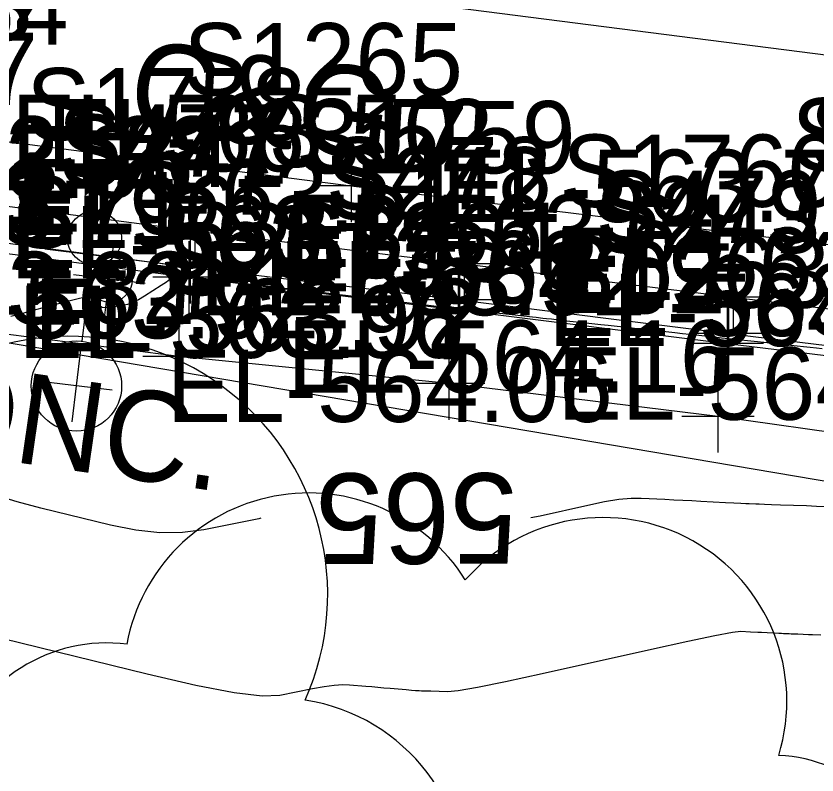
# Model space of a CAD drawing. Extents: x 1724534 to 1727318, y 657156 to 660047.
# Drawn here: x 1725337.13 to 1725381.44, y 658574.44 to 658616.4 of the extents above; entities that cross this region are included whole.
import ezdxf

# ---------------------------------------------------------------- set-up
doc = ezdxf.new("R2010")
doc.units = 0
for name, color, linetype in [('SURVEY - CONTOURS - Index with Text', 7, 'Continuous'), ('SURVEY - CONTOURS - Intermediate with optional Text', 7, 'Continuous'), ('SURVEY - DTM - Breaklines', 7, 'Continuous'), ('SURVEY - DTM - Breaklines - Points - Elevations', 7, 'Continuous'), ('SURVEY - DTM - Breaklines - Points - Locators', 7, 'Continuous'), ('SURVEY - DTM - Breaklines - Points - Numbers', 7, 'Continuous'), ('SURVEY - PROPERTY - Property Markers with Text', 7, 'Continuous'), ('SURVEY - TRAFFIC CONTROL - Pavement Marking - Points - Numbers', 7, 'Continuous'), ('SURVEY - TRAFFIC CONTROL - Pavement Marking with Text', 7, 'Continuous'), ('SURVEY - TRAFFIC CONTROL - Signs - Points - Elevations', 7, 'Continuous'), ('SURVEY - TRAFFIC CONTROL - Signs - Points - Locators', 7, 'Continuous'), ('SURVEY - TRAFFIC CONTROL - Signs - Points - Numbers', 7, 'Continuous'), ('SURVEY - TRAFFIC CONTROL - Signs and Devices with Text', 7, 'Continuous'), ('SURVEY - TRANSPORTATION - Features', 7, 'Continuous'), ('SURVEY - TRANSPORTATION - Features - Points - Elevations', 7, 'Continuous'), ('SURVEY - TRANSPORTATION - Features - Points - Locators', 7, 'Continuous'), ('SURVEY - TRANSPORTATION - Features - Points - Numbers', 7, 'Continuous'), ('SURVEY - TRANSPORTATION - Features Text', 7, 'Continuous'), ('SURVEY - TRANSPORTATION - Roads', 7, 'Continuous'), ('SURVEY - TRANSPORTATION - Roads - Points - Elevations', 7, 'Continuous'), ('SURVEY - TRANSPORTATION - Roads - Points - Locators', 7, 'Continuous'), ('SURVEY - TRANSPORTATION - Roads - Points - Numbers', 7, 'Continuous'), ('SURVEY - UTILITIES - Electric (Lighting) - Points - Elevations', 7, 'Continuous'), ('SURVEY - UTILITIES - Electric (Lighting) - Points - Locators', 7, 'Continuous'), ('SURVEY - UTILITIES - Electric (Lighting) - Points - Numbers', 7, 'Continuous'), ('SURVEY - UTILITIES - Electric (Lighting) with Text', 7, 'Continuous'), ('SURVEY - UTILITIES - Fiber Optic Cable (Underground) with Text', 7, 'Continuous'), ('SURVEY - UTILITIES - Gas - Points - Elevations', 7, 'Continuous'), ('SURVEY - UTILITIES - Gas - Points - Numbers', 7, 'Continuous'), ('SURVEY - VEGETATION - Features with Text', 7, 'Continuous')]:
    doc.layers.add(name, color=color, linetype=linetype)

msp = doc.modelspace()

# ---------------------------------------------------------------- linework, layer by layer
at = {"layer": 'SURVEY - CONTOURS - Index with Text'}
for points in [[(1725350.676, 658588.635), (1725350.563, 658588.614), (1725347.522, 658588.005), (1725346.343, 658587.849), (1725345.09, 658587.839), (1725343.76, 658587.974), (1725342.356, 658588.256), (1725338.508, 658589.2), (1725337.195, 658589.54), (1725336.141, 658589.853)], [(1725381.955, 658589.274), (1725381.401, 658589.295), (1725380.857, 658589.315), (1725379.417, 658589.37), (1725378.926, 658589.388), (1725378.536, 658589.403), (1725378.246, 658589.414), (1725378.056, 658589.421), (1725377.683, 658589.435), (1725377.496, 658589.443), (1725377.217, 658589.456), (1725376.846, 658589.474), (1725376.381, 658589.498), (1725375.019, 658589.568), (1725374.511, 658589.594), (1725374.008, 658589.62), (1725373.51, 658589.646), (1725373.017, 658589.671), (1725371.709, 658589.738), (1725371.157, 658589.733), (1725370.48, 658589.666), (1725369.679, 658589.538), (1725368.754, 658589.349), (1725366.12, 658588.762), (1725365.603, 658588.657)]]:
    msp.add_lwpolyline(points, dxfattribs=at)
at = {"layer": 'SURVEY - CONTOURS - Intermediate with optional Text'}
for points in [[(1725381.732, 658597.999), (1725381.415, 658598.033), (1725381.067, 658598.071), (1725380.687, 658598.112), (1725379.634, 658598.226), (1725379.244, 658598.268), (1725378.866, 658598.309), (1725378.498, 658598.349), (1725378.142, 658598.387), (1725376.681, 658598.543), (1725376.549, 658598.557), (1725376.505, 658598.562), (1725376.467, 658598.566), (1725376.351, 658598.579), (1725376.158, 658598.6), (1725375.888, 658598.629), (1725375.066, 658598.72), (1725374.741, 658598.755), (1725374.385, 658598.795), (1725373.996, 658598.838), (1725373.575, 658598.884), (1725372.409, 658599.013), (1725371.336, 658599.131), (1725371.084, 658599.159), (1725370.219, 658599.254), (1725369.883, 658599.291), (1725369.474, 658599.336), (1725368.991, 658599.389), (1725367.605, 658599.543), (1725367.132, 658599.595), (1725366.753, 658599.637), (1725366.468, 658599.668), (1725366.278, 658599.689), (1725365.895, 658599.731), (1725365.694, 658599.753), (1725364.404, 658599.896), (1725362.799, 658600.073), (1725361.896, 658600.173), (1725361.67, 658600.198), (1725361.595, 658600.206), (1725361.595, 658600.206), (1725361.586, 658600.207), (1725361.561, 658600.21), (1725361.52, 658600.215), (1725361.461, 658600.222), (1725361.284, 658600.242), (1725361.141, 658600.259), (1725360.845, 658600.294), (1725357.986, 658600.635), (1725357.386, 658600.706), (1725356.656, 658600.793), (1725356.525, 658600.809), (1725356.386, 658600.825), (1725356.254, 658600.84), (1725355.961, 658600.875), (1725355.509, 658600.929), (1725354.897, 658601.002), (1725353.05, 658601.222), (1725352.439, 658601.295), (1725351.992, 658601.348), (1725351.708, 658601.382), (1725351.363, 658601.423), (1725351.074, 658601.457), (1725349.995, 658601.586), (1725348.112, 658601.81), (1725347.494, 658601.884), (1725347.053, 658601.937), (1725346.788, 658601.968), (1725346.699, 658601.979), (1725346.698, 658601.979), (1725346.698, 658601.979), (1725346.698, 658601.979), (1725346.698, 658601.979), (1725346.698, 658601.979), (1725346.602, 658601.99), (1725346.483, 658602.004), (1725345.428, 658602.125), (1725345.725, 658601.996), (1725345.738, 658601.944), (1725345.648, 658601.844), (1725345.455, 658601.695), (1725345.159, 658601.499), (1725344.235, 658600.91), (1725343.898, 658600.712), (1725343.583, 658600.56), (1725343.289, 658600.454), (1725343.016, 658600.393), (1725342.316, 658600.292), (1725342.081, 658600.274), (1725341.903, 658600.296), (1725341.78, 658600.357), (1725341.714, 658600.458), (1725341.613, 658600.78), (1725341.515, 658600.869), (1725341.297, 658600.894), (1725340.959, 658600.856), (1725340.501, 658600.753), (1725339.121, 658600.396), (1725338.635, 658600.27), (1725338.212, 658600.159), (1725337.853, 658600.064), (1725337.557, 658599.984), (1725336.852, 658599.792)], [(1725381.641, 658582.175), (1725381.186, 658582.193), (1725380.963, 658582.201), (1725380.375, 658582.223), (1725380.175, 658582.231), (1725380.016, 658582.237), (1725379.897, 658582.241), (1725379.82, 658582.244), (1725379.667, 658582.25), (1725379.591, 658582.253), (1725379.477, 658582.259), (1725379.326, 658582.266), (1725378.372, 658582.315), (1725378.167, 658582.326), (1725377.762, 658582.346), (1725377.228, 658582.374), (1725376.769, 658582.32), (1725375.793, 658582.136), (1725374.299, 658581.824), (1725372.287, 658581.383), (1725366.233, 658580.034), (1725364.203, 658579.593), (1725362.655, 658579.28), (1725361.588, 658579.097), (1725361.003, 658579.042), (1725360.083, 658579.069), (1725359.782, 658579.077), (1725359.566, 658579.083), (1725359.437, 658579.087), (1725359.394, 658579.088), (1725359.394, 658579.088), (1725359.351, 658579.092), (1725359.225, 658579.103), (1725359.014, 658579.121), (1725358.719, 658579.146), (1725357.82, 658579.223), (1725357.483, 658579.252), (1725357.147, 658579.281), (1725356.811, 658579.309), (1725356.475, 658579.338), (1725355.58, 658579.415), (1725355.201, 658579.423), (1725354.735, 658579.389), (1725354.181, 658579.314), (1725353.54, 658579.198), (1725351.715, 658578.832), (1725350.743, 658578.804), (1725349.197, 658578.992), (1725347.075, 658579.399), (1725344.379, 658580.023), (1725336.421, 658581.976)]]:
    msp.add_lwpolyline(points, dxfattribs=at)
at = {"layer": 'SURVEY - DTM - Breaklines'}
msp.add_lwpolyline([(1725331.824, 658603.91), (1725346.697, 658601.959), (1725361.588, 658600.154), (1725376.473, 658598.302), (1725392.698, 658596.322), (1725399.855, 658595.486), (1725403.823, 658594.981), (1725407.789, 658594.463), (1725413.94, 658593.597), (1725423.536, 658592.349), (1725438.414, 658590.44), (1725459.817, 658587.804), (1725465.092, 658587.122), (1725470.394, 658586.443), (1725479.975, 658585.259), (1725489.875, 658584.035), (1725509.601, 658581.531)], dxfattribs=at)
at = {"layer": 'SURVEY - DTM - Breaklines - Points - Locators'}
for p, q in [((1725346.697, 658603.959), (1725346.697, 658599.959)), ((1725348.697, 658601.959), (1725344.697, 658601.959)), ((1725361.588, 658602.154), (1725361.588, 658598.154)), ((1725363.588, 658600.154), (1725359.588, 658600.154)), ((1725376.473, 658600.302), (1725376.473, 658596.302)), ((1725378.473, 658598.302), (1725374.473, 658598.302))]:
    msp.add_line(p, q, dxfattribs=at)
at = {"layer": 'SURVEY - TRAFFIC CONTROL - Pavement Marking with Text'}
msp.add_lwpolyline([(1725300.946, 658624.76), (1725346.56, 658618.791), (1725386.237, 658613.711), (1725391.405, 658613.061)], dxfattribs=at)
at = {"layer": 'SURVEY - TRAFFIC CONTROL - Signs - Points - Locators'}
for p, q in [((1725342.048, 658599.874), (1725342.534, 658603.844)), ((1725344.276, 658601.616), (1725340.306, 658602.102))]:
    msp.add_line(p, q, dxfattribs=at)
at = {"layer": 'SURVEY - TRAFFIC CONTROL - Signs and Devices with Text'}
msp.add_line((1725338.717, 658603.53), (1725346.162, 658602.619), dxfattribs=at)
msp.add_circle((1725342.309, 658601.831), 1.25, dxfattribs=at)
at = {"layer": 'SURVEY - TRANSPORTATION - Features'}
for points in [[(1725400.221, 658571.848), (1725399.893, 658576.832), (1725400.098, 658582.049), (1725399.251, 658589.894), (1725399.287, 658591.018), (1725392.146, 658591.982), (1725375.96, 658594.271), (1725361.07, 658596.084), (1725346.14, 658597.578), (1725331.263, 658599.505), (1725316.379, 658601.372), (1725301.242, 658603.491), (1725296.828, 658604.193), (1725291.122, 658605.02), (1725282.388, 658606.385), (1725277.767, 658607.035), (1725264.868, 658608.95), (1725250.092, 658611.569), (1725235.272, 658613.802), (1725224.442, 658615.275)], [(1725332.152, 658606.481), (1725347.025, 658604.53), (1725361.914, 658602.705), (1725376.797, 658600.853), (1725393.024, 658598.885), (1725400.172, 658597.98), (1725404.14, 658597.475), (1725408.106, 658596.957), (1725414.257, 658596.09), (1725423.854, 658594.843), (1725438.731, 658592.934), (1725460.134, 658590.297), (1725465.409, 658589.616), (1725470.711, 658588.936), (1725480.292, 658587.752), (1725490.2, 658586.59), (1725509.954, 658584.046)], [(1725331.895, 658604.466), (1725346.768, 658602.515), (1725361.659, 658600.71), (1725376.543, 658598.858), (1725392.77, 658596.889), (1725399.927, 658596.053), (1725403.895, 658595.548), (1725407.861, 658595.03), (1725414.012, 658594.163), (1725423.609, 658592.916), (1725438.486, 658591.007), (1725459.889, 658588.37), (1725465.164, 658587.689), (1725470.466, 658587.009), (1725480.047, 658585.825), (1725489.947, 658584.602), (1725509.681, 658582.097)]]:
    msp.add_lwpolyline(points, dxfattribs=at)
at = {"layer": 'SURVEY - TRANSPORTATION - Features - Points - Locators'}
for p, q in [((1725347.025, 658606.53), (1725347.025, 658602.53)), ((1725349.025, 658604.53), (1725345.025, 658604.53)), ((1725346.768, 658604.515), (1725346.768, 658600.515)), ((1725361.914, 658604.705), (1725361.914, 658600.705)), ((1725363.914, 658602.705), (1725359.914, 658602.705)), ((1725361.659, 658602.71), (1725361.659, 658598.71)), ((1725376.797, 658602.853), (1725376.797, 658598.853)), ((1725348.768, 658602.515), (1725344.768, 658602.515)), ((1725363.659, 658600.71), (1725359.659, 658600.71)), ((1725378.797, 658600.853), (1725374.797, 658600.853)), ((1725376.543, 658600.858), (1725376.543, 658596.858)), ((1725346.14, 658599.578), (1725346.14, 658595.578)), ((1725378.543, 658598.858), (1725374.543, 658598.858)), ((1725361.07, 658598.084), (1725361.07, 658594.084)), ((1725348.14, 658597.578), (1725344.14, 658597.578)), ((1725363.07, 658596.084), (1725359.07, 658596.084)), ((1725375.96, 658596.271), (1725375.96, 658592.271)), ((1725377.96, 658594.271), (1725373.96, 658594.271))]:
    msp.add_line(p, q, dxfattribs=at)
at = {"layer": 'SURVEY - TRANSPORTATION - Roads'}
msp.add_lwpolyline([(1725141.865, 658637.665), (1725195.259, 658629.577), (1725266.454, 658618.825), (1725280.298, 658616.735), (1725282.277, 658616.45), (1725304.066, 658613.404), (1725306.05, 658613.154), (1725331.867, 658610.059), (1725333.852, 658609.816), (1725355.673, 658607.015), (1725389.419, 658602.863), (1725393.39, 658602.389), (1725395.376, 658602.145), (1725397.115, 658601.908), (1725399.346, 658601.658), (1725421.182, 658598.991), (1725423.165, 658598.737), (1725435.064, 658597.189), (1725446.969, 658595.689), (1725460.854, 658593.916), (1725508.47, 658587.877)], dxfattribs=at)
at = {"layer": 'SURVEY - TRANSPORTATION - Roads - Points - Locators'}
for p, q in [((1725355.673, 658609.015), (1725355.673, 658605.015)), ((1725357.673, 658607.015), (1725353.673, 658607.015))]:
    msp.add_line(p, q, dxfattribs=at)
at = {"layer": 'SURVEY - UTILITIES - Electric (Lighting) - Points - Locators'}
for p, q in [((1725340.705, 658597.947), (1725340.219, 658593.977)), ((1725342.447, 658595.719), (1725338.477, 658596.205))]:
    msp.add_line(p, q, dxfattribs=at)
at = {"layer": 'SURVEY - UTILITIES - Electric (Lighting) with Text'}
msp.add_line((1725341.293, 658602.651), (1725340.777, 658598.432), dxfattribs=at)
for centre, radius in [((1725341.475, 658604.139), 1.5), ((1725340.473, 658595.95), 2.5)]:
    msp.add_circle(centre, radius, dxfattribs=at)
at = {"layer": 'SURVEY - UTILITIES - Fiber Optic Cable (Underground) with Text'}
msp.add_line((1725528.948, 658565.808), (1725219.136, 658618.198), dxfattribs=at)
at = {"layer": 'SURVEY - VEGETATION - Features with Text'}
for centre, radius, start, end in [((1725340.09, 658584.419), 14.281, 335.8905, 131.7289), ((1725353.312, 658579.812), 10.222, 31.9683, 169.4925), ((1725369.613, 658578.521), 10.156, 342.8641, 138.7026), ((1725342.177, 658572.773), 8.971, 82.9155, 239.7044), ((1725351.504, 658568.179), 10.532, 266.1434, 81.1436), ((1725379.072, 658568.043), 7.49, 273.117, 88.1173)]:
    msp.add_arc(centre, radius, start, end, dxfattribs=at)

# ---------------------------------------------------------------- texts
at = {"layer": 'SURVEY - CONTOURS - Index with Text'}
msp.add_text('565', height=5, rotation=180.0851, dxfattribs=at).set_placement((1725364.861, 658591.128))
at = {"layer": 'SURVEY - DTM - Breaklines - Points - Elevations'}
for s, p in [('EL-563.71', (1725321.94, 658603.777)), ('EL-563.81', (1725336.824, 658601.91)), ('EL-564.02', (1725351.697, 658599.959)), ('EL-564.04', (1725366.588, 658598.154))]:
    msp.add_text(s, height=4, dxfattribs=at).set_placement(p)
at = {"layer": 'SURVEY - DTM - Breaklines - Points - Numbers'}
for s, p in [('S241', (1725339.519, 658606.959)), ('S242', (1725354.252, 658605.154)), ('S243', (1725369.137, 658603.302))]:
    msp.add_text(s, height=4, dxfattribs=at).set_placement(p)
at = {"layer": 'SURVEY - PROPERTY - Property Markers with Text'}
msp.add_text('CONC.', height=5.0001, rotation=351.7546, dxfattribs=at).set_placement((1725326.966, 658593.203))
at = {"layer": 'SURVEY - TRAFFIC CONTROL - Pavement Marking - Points - Numbers'}
msp.add_text('S1834', height=4, dxfattribs=at).set_placement((1725381.024, 658607.936))
at = {"layer": 'SURVEY - TRAFFIC CONTROL - Signs - Points - Elevations'}
msp.add_text('EL-563.92', height=4, dxfattribs=at).set_placement((1725347.291, 658599.859))
at = {"layer": 'SURVEY - TRAFFIC CONTROL - Signs - Points - Numbers'}
msp.add_text('S2128', height=4, dxfattribs=at).set_placement((1725332.956, 658606.859))
at = {"layer": 'SURVEY - TRANSPORTATION - Features - Points - Elevations'}
for s, p in [('EL-563.36', (1725322.268, 658606.347)), ('EL-563.51', (1725337.152, 658604.481)), ('EL-563.23', (1725322.011, 658604.333)), ('EL-563.34', (1725336.895, 658602.466)), ('EL-563.64', (1725352.025, 658602.53)), ('EL-563.52', (1725351.768, 658600.515)), ('EL-563.74', (1725366.914, 658600.705)), ('EL-563.82', (1725322.379, 658599.372)), ('EL-563.59', (1725366.659, 658598.71)), ('EL-563.96', (1725337.263, 658597.505)), ('EL-564.16', (1725352.14, 658595.578)), ('EL-564.18', (1725367.07, 658594.084))]:
    msp.add_text(s, height=4, dxfattribs=at).set_placement(p)
at = {"layer": 'SURVEY - TRANSPORTATION - Features - Points - Numbers'}
for s, p in [('S1757', (1725322.864, 658611.481)), ('S1758', (1725337.69, 658609.53)), ('S477', (1725339.432, 658607.515)), ('S1759', (1725352.611, 658607.705)), ('S478', (1725354.276, 658605.71)), ('S1760', (1725367.336, 658605.853)), ('S1965', (1725336.852, 658603.578)), ('S479', (1725369.191, 658603.858)), ('S1964', (1725351.782, 658602.084)), ('S1963', (1725366.672, 658600.271))]:
    msp.add_text(s, height=4, dxfattribs=at).set_placement(p)
at = {"layer": 'SURVEY - TRANSPORTATION - Features Text'}
msp.add_text('C&G', height=5, rotation=353.0887, dxfattribs=at).set_placement((1725343.207, 658610.134))
at = {"layer": 'SURVEY - TRANSPORTATION - Roads - Points - Elevations'}
for s, p in [('EL-563.50', (1725336.867, 658608.059)), ('EL-563.52', (1725338.852, 658607.816)), ('EL-563.73', (1725360.673, 658605.015))]:
    msp.add_text(s, height=4, dxfattribs=at).set_placement(p)
at = {"layer": 'SURVEY - TRANSPORTATION - Roads - Points - Numbers'}
for s, p in [('S1263', (1725322.579, 658615.059)), ('S1264', (1725324.564, 658614.816)), ('S1265', (1725346.385, 658612.015)), ('S1266', (1725380.021, 658607.863))]:
    msp.add_text(s, height=4, dxfattribs=at).set_placement(p)
at = {"layer": 'SURVEY - UTILITIES - Electric (Lighting) - Points - Elevations'}
msp.add_text('EL-564.06', height=4, dxfattribs=at).set_placement((1725345.462, 658593.962))
at = {"layer": 'SURVEY - UTILITIES - Electric (Lighting) - Points - Numbers'}
msp.add_text('S2073', height=4, dxfattribs=at).set_placement((1725345.462, 658600.962))
at = {"layer": 'SURVEY - UTILITIES - Gas - Points - Elevations'}
for p in [(1725329.211, 658598.581), (1725338.139, 658597.875)]:
    msp.add_text('EL-563.92', height=4, dxfattribs=at).set_placement(p)
at = {"layer": 'SURVEY - UTILITIES - Gas - Points - Numbers'}
msp.add_text('S5311', height=4, dxfattribs=at).set_placement((1725324.009, 658604.875))

doc.saveas('drawing.dxf')
